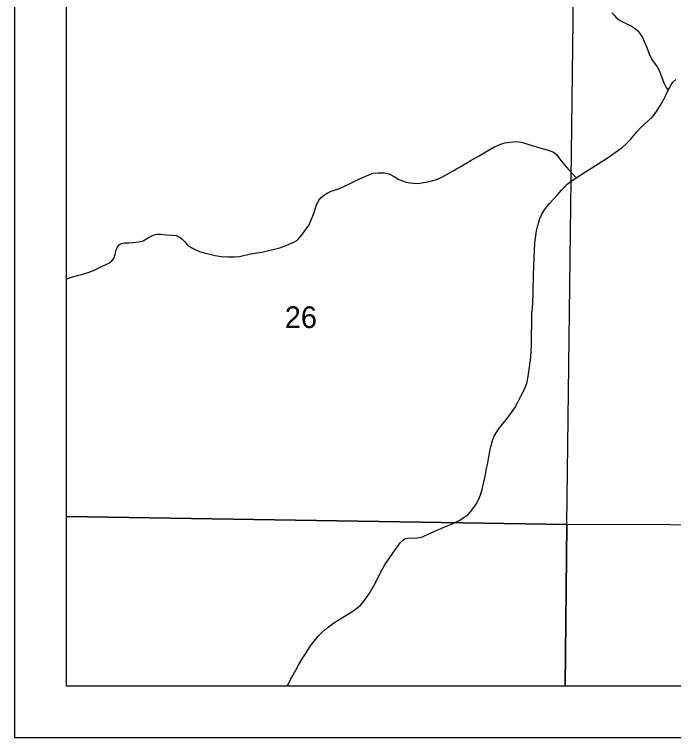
# Model space of a CAD drawing. Extents: x 0 to 34, y 0 to 22.
# Drawn here: x 2 to 3.275, y 14 to 15.399 of the extents above; entities that cross this region are included whole.
import ezdxf

# ---------------------------------------------------------------- set-up
doc = ezdxf.new("R2010")
doc.units = 0
for name, color, linetype in [('GM_X_Corporation', 7, 'Continuous'), ('GM_X_Section_Text', 7, 'Continuous'), ('GM_X_Township_Road', 7, 'Continuous'), ('GM_X_Township_Text', 7, 'Continuous'), ('SH_Data', 7, 'Continuous')]:
    doc.layers.add(name, color=color, linetype=linetype)

msp = doc.modelspace()

# ---------------------------------------------------------------- linework, layer by layer
at = {"layer": 'GM_X_Corporation'}
for points in [[(2.1, 15.4568), (2.1, 14.4279), (3.0687, 14.4122), (3.0813, 15.4398)], [(3.0813, 15.4398), (4.0887, 15.4288), (4.0718, 14.4088), (3.0687, 14.4122)], [(2.1, 14.4279), (2.1, 14.1), (3.065, 14.1), (3.0687, 14.4122)], [(3.065, 14.1), (4.0712, 14.1), (4.0718, 14.4088), (3.0687, 14.4122)]]:
    msp.add_lwpolyline(points, close=True, dxfattribs=at)
at = {"layer": 'GM_X_Township_Road'}
for points in [[(3.1555, 15.4026), (3.1597, 15.3977), (3.1633, 15.3939), (3.1676, 15.3903), (3.1719, 15.3875), (3.1764, 15.3852), (3.1817, 15.3825), (3.1867, 15.3802), (3.1917, 15.3779), (3.1973, 15.3743), (3.2014, 15.3712), (3.2055, 15.3679), (3.2095, 15.3625), (3.2145, 15.3545), (3.2201, 15.3427), (3.2233, 15.3352), (3.2275, 15.3229), (3.2331, 15.3121), (3.2432, 15.2978), (3.2476, 15.2899), (3.2511, 15.2806), (3.2558, 15.2669), (3.2608, 15.2577), (3.2643, 15.2529)], [(2.5278, 14.1), (2.529, 14.1019), (2.5367, 14.1168), (2.544, 14.1304), (2.5503, 14.1412), (2.5568, 14.1523), (2.5642, 14.164), (2.5729, 14.1776), (2.5801, 14.1873), (2.5881, 14.1971), (2.5936, 14.2025), (2.6007, 14.2091), (2.6094, 14.2158), (2.618, 14.2222), (2.6342, 14.2321), (2.6545, 14.2446), (2.6648, 14.252), (2.6692, 14.2561), (2.6766, 14.2645), (2.6821, 14.2728), (2.6874, 14.2803), (2.6959, 14.2948), (2.7037, 14.31), (2.7088, 14.3205), (2.7172, 14.3352), (2.7319, 14.3567), (2.7406, 14.3697), (2.7464, 14.3774), (2.7509, 14.3818), (2.7552, 14.3846), (2.7601, 14.386), (2.7657, 14.3863), (2.7764, 14.3858), (2.783, 14.3868), (2.7892, 14.3887), (2.8031, 14.395), (2.8116, 14.3986), (2.8191, 14.402), (2.8251, 14.4047), (2.8302, 14.4068), (2.8356, 14.4091), (2.8431, 14.412), (2.8513, 14.4155), (2.8601, 14.42), (2.8675, 14.4243), (2.8773, 14.4316), (2.882, 14.437), (2.8869, 14.4425), (2.8932, 14.4516), (2.8971, 14.4584), (2.8998, 14.4644), (2.9023, 14.4714), (2.9048, 14.4798), (2.9104, 14.5059), (2.9126, 14.5176), (2.9154, 14.5319), (2.9179, 14.5469), (2.9209, 14.5608), (2.9253, 14.5766), (2.9281, 14.5829), (2.932, 14.5899), (2.9365, 14.5966), (2.9419, 14.6037), (2.949, 14.6128), (2.9548, 14.6201), (2.9679, 14.6382), (2.9735, 14.6488), (2.9795, 14.6609), (2.9863, 14.674), (2.9894, 14.6809), (2.9915, 14.6877), (2.9946, 14.703), (2.9959, 14.7125), (2.9987, 14.7358), (3, 14.7595), (3.001, 14.8194), (3.0024, 14.8401), (3.0031, 14.8632), (3.004, 14.8949), (3.0054, 14.9274), (3.0058, 14.9421), (3.0067, 14.957), (3.0099, 14.9807), (3.0125, 14.9912), (3.0141, 14.9976), (3.0162, 15.0047), (3.0201, 15.0128), (3.0241, 15.0196), (3.0291, 15.0263), (3.0352, 15.0336), (3.0406, 15.0399), (3.0505, 15.0505), (3.0581, 15.0596), (3.0641, 15.0654), (3.0692, 15.0707), (3.0762, 15.0759), (3.0865, 15.0834), (3.1044, 15.0949), (3.1482, 15.1225), (3.1666, 15.1353), (3.1761, 15.1425), (3.1826, 15.148), (3.1883, 15.1538), (3.1916, 15.1574), (3.1955, 15.1621), (3.204, 15.1723), (3.2119, 15.1805), (3.2195, 15.1876), (3.2342, 15.201), (3.2404, 15.2096), (3.2467, 15.2189), (3.2528, 15.2289), (3.2581, 15.2393), (3.2604, 15.2444), (3.2643, 15.2529), (3.2695, 15.2619), (3.2732, 15.2682), (3.279, 15.2737)], [(2.1, 14.887), (2.1014, 14.8876), (2.1121, 14.8915), (2.1216, 14.894), (2.1297, 14.8963), (2.1423, 14.9), (2.1528, 14.9039), (2.1631, 14.9088), (2.1719, 14.9133), (2.1774, 14.9157), (2.1835, 14.9184), (2.1884, 14.9225), (2.192, 14.9268), (2.1947, 14.9346), (2.1968, 14.944), (2.1991, 14.949), (2.2027, 14.9534), (2.2068, 14.9561), (2.212, 14.9572), (2.221, 14.9575), (2.2296, 14.9578), (2.2407, 14.959), (2.2489, 14.9614), (2.2562, 14.9658), (2.268, 14.9719), (2.2726, 14.9738), (2.2759, 14.9744), (2.2824, 14.9741), (2.2881, 14.9732), (2.2935, 14.9727), (2.3048, 14.9721), (2.3128, 14.9713), (2.3168, 14.9699), (2.3206, 14.9675), (2.3245, 14.9644), (2.329, 14.9598), (2.3333, 14.9549), (2.3374, 14.9517), (2.3432, 14.9477), (2.3496, 14.9443), (2.3582, 14.9407), (2.3695, 14.9376), (2.3777, 14.9355), (2.3883, 14.9329), (2.3995, 14.9308), (2.4119, 14.93), (2.4257, 14.93), (2.4355, 14.9308), (2.4565, 14.9359), (2.4782, 14.9394), (2.4948, 14.9432), (2.5132, 14.9475), (2.5255, 14.9525), (2.5418, 14.9593), (2.5459, 14.962), (2.5495, 14.9648), (2.5568, 14.9733), (2.5702, 14.9924), (2.5799, 15.016), (2.5838, 15.0291), (2.5887, 15.04), (2.5928, 15.0445), (2.598, 15.0491), (2.605, 15.0538), (2.6128, 15.0572), (2.627, 15.0619), (2.643, 15.0691), (2.6649, 15.0799), (2.6857, 15.0892), (2.694, 15.0919), (2.7033, 15.0928), (2.7155, 15.0927), (2.7249, 15.0909), (2.7347, 15.086), (2.7437, 15.0802), (2.7503, 15.0771), (2.7574, 15.0749), (2.7652, 15.0732), (2.772, 15.0727), (2.7805, 15.0725), (2.7878, 15.0735), (2.7994, 15.0753), (2.8167, 15.08), (2.8265, 15.0842), (2.8383, 15.0911), (2.8476, 15.0961), (2.8553, 15.1007), (2.8634, 15.1053), (2.8749, 15.1122), (2.8833, 15.1172), (2.8989, 15.1256), (2.9148, 15.1352), (2.9272, 15.1422), (2.9405, 15.148), (2.9487, 15.1508), (2.959, 15.1523), (2.9705, 15.1532), (2.9799, 15.1519), (2.9893, 15.1497), (2.999, 15.1465), (3.0343, 15.1362), (3.0412, 15.1335), (3.0448, 15.1315), (3.0485, 15.1283), (3.059, 15.1138), (3.0722, 15.0984), (3.0865, 15.0834)]]:
    msp.add_lwpolyline(points, dxfattribs=at)
at = {"layer": 'GM_X_Township_Text'}
msp.add_lwpolyline([(2.6249, 19.1744), (2.6223, 19.0497), (2.622, 19.0358), (2.6202, 18.9481), (2.604, 17.9706), (2.6039, 17.9669), (2.5791, 16.4754), (2.4938, 16.4762), (2.1, 16.4804), (2.1, 14.1), (7.1227, 14.1)], dxfattribs=at)
at = {"layer": 'SH_Data'}
for p, q in [((2, 21), (2, 14)), ((2.1, 20.9), (2.1, 14.1)), ((2.1, 14.1), (8.9, 14.1)), ((2.1, 14.1), (2.1, 14.1)), ((2, 14), (9, 14))]:
    msp.add_line(p, q, dxfattribs=at)

# ---------------------------------------------------------------- texts
at = {"layer": 'GM_X_Section_Text'}
msp.add_text('26', height=0.04186, rotation=0, dxfattribs=at).set_placement((2.5229, 14.7925))

doc.saveas('drawing.dxf')
